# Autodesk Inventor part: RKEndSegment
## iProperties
Company: Scholle und Partner GmbH
Shininess: 64.0
Length Units: 11269
Angle Units: 11279
Time Units: 11290
Mass Units: 11283
Length Display Precision: 3
Angle Display Precision: 2
Compacted: True
Part Number: RKEndSegment
Document SubType Name: Sheet Metal
Created: 2004-10
Material: Standard
Designer: mp
Density: 0.0
Volumn: 0.0
Area: 0.0
PropertySet Name: Model Information
Control State: 0
Master: False
Checked Out: False
Author: Michael Puschner
Comments: www.scholle.de
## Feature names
1. Extrusion1
2. ExtrusionAbwicklung1
